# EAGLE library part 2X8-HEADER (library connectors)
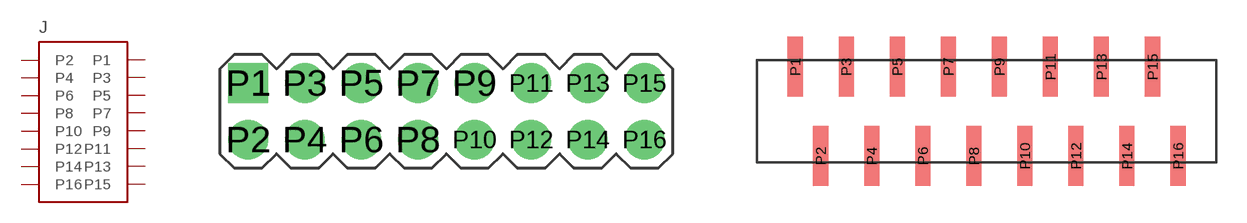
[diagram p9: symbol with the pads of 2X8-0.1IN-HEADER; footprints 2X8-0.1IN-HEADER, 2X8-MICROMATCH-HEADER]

Designator prefix J

## 2X8-HEADER0.1IN  [2X8-0.1IN-HEADER]
P1  P1  pas
P2  P2  pas
P3  P3  pas
P4  P4  pas
P5  P5  pas
P6  P6  pas
P7  P7  pas
P8  P8  pas
P9  P9  pas
P10  P10  pas
P11  P11  pas
P12  P12  pas
P13  P13  pas
P14  P14  pas
P15  P15  pas
P16  P16  pas

## 2X8-HEADERMICROMATCH  [2X8-MICROMATCH-HEADER]
Pads as for 2X8-0.1IN-HEADER

## Footprint 2X8-0.1IN-HEADER (pad centres in mm)
drill 1.05 pad 1.778 square: P1 -8.89,1.27
drill 1.05 pad 1.778 round: P2 -8.89,-1.27; P3 -6.35,1.27; P4 -6.35,-1.27; P5 -3.81,1.27; P6 -3.81,-1.27; P7 -1.27,1.27; P8 -1.27,-1.27; P9 1.27,1.27; P10 1.27,-1.27; P11 3.81,1.27; P12 3.81,-1.27; P13 6.35,1.27; P14 6.35,-1.27; P15 8.89,1.27; P16 8.89,-1.27

## Footprint 2X8-MICROMATCH-HEADER (pad centres in mm)
smd 0.75 x 3: P1 -9.525,2.223; P2 -8.255,-2.223; P3 -6.985,2.223; P4 -5.715,-2.223; P5 -4.445,2.223; P6 -3.175,-2.223; P7 -1.905,2.223; P8 -0.635,-2.223; P9 0.635,2.223; P10 1.905,-2.223; P11 3.175,2.223; P12 4.445,-2.223; P13 5.715,2.223; P14 6.985,-2.223; P15 8.255,2.223; P16 9.525,-2.223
